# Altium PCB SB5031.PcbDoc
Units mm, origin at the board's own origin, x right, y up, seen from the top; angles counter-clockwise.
Board outline 152.4 x 101.6 mm, 2 copper layers (Top Layer, Bottom Layer); 0 components, 0 nets, 4 pads, 0 vias.
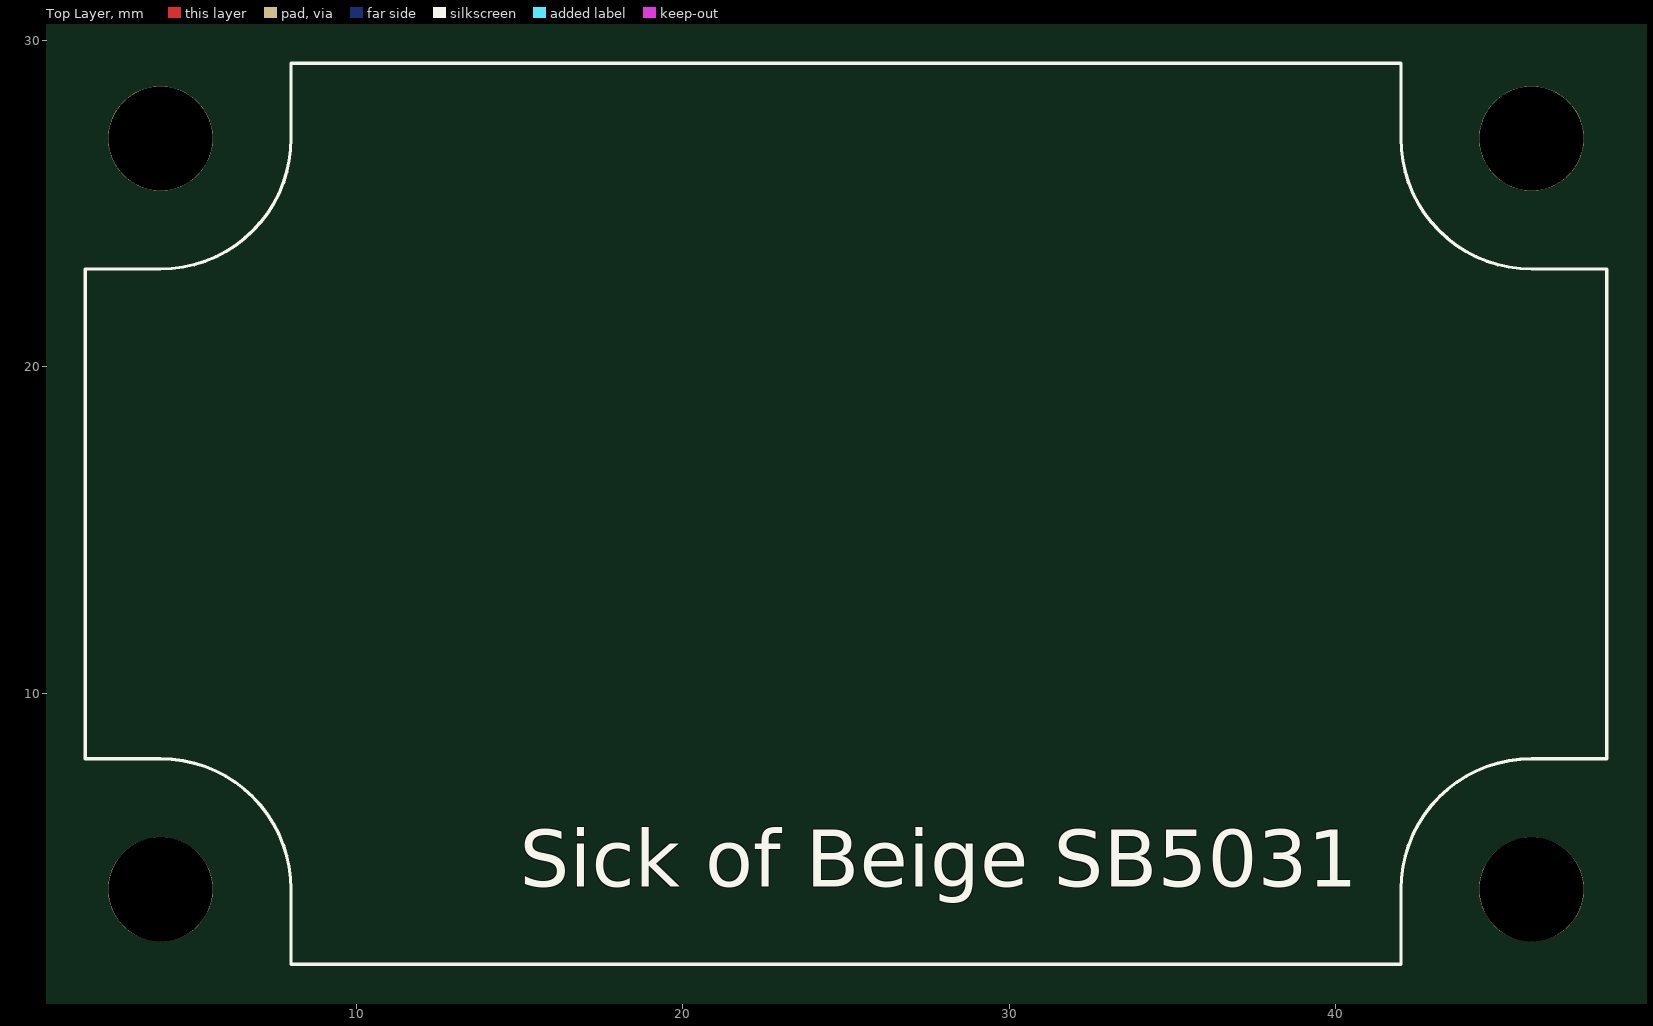
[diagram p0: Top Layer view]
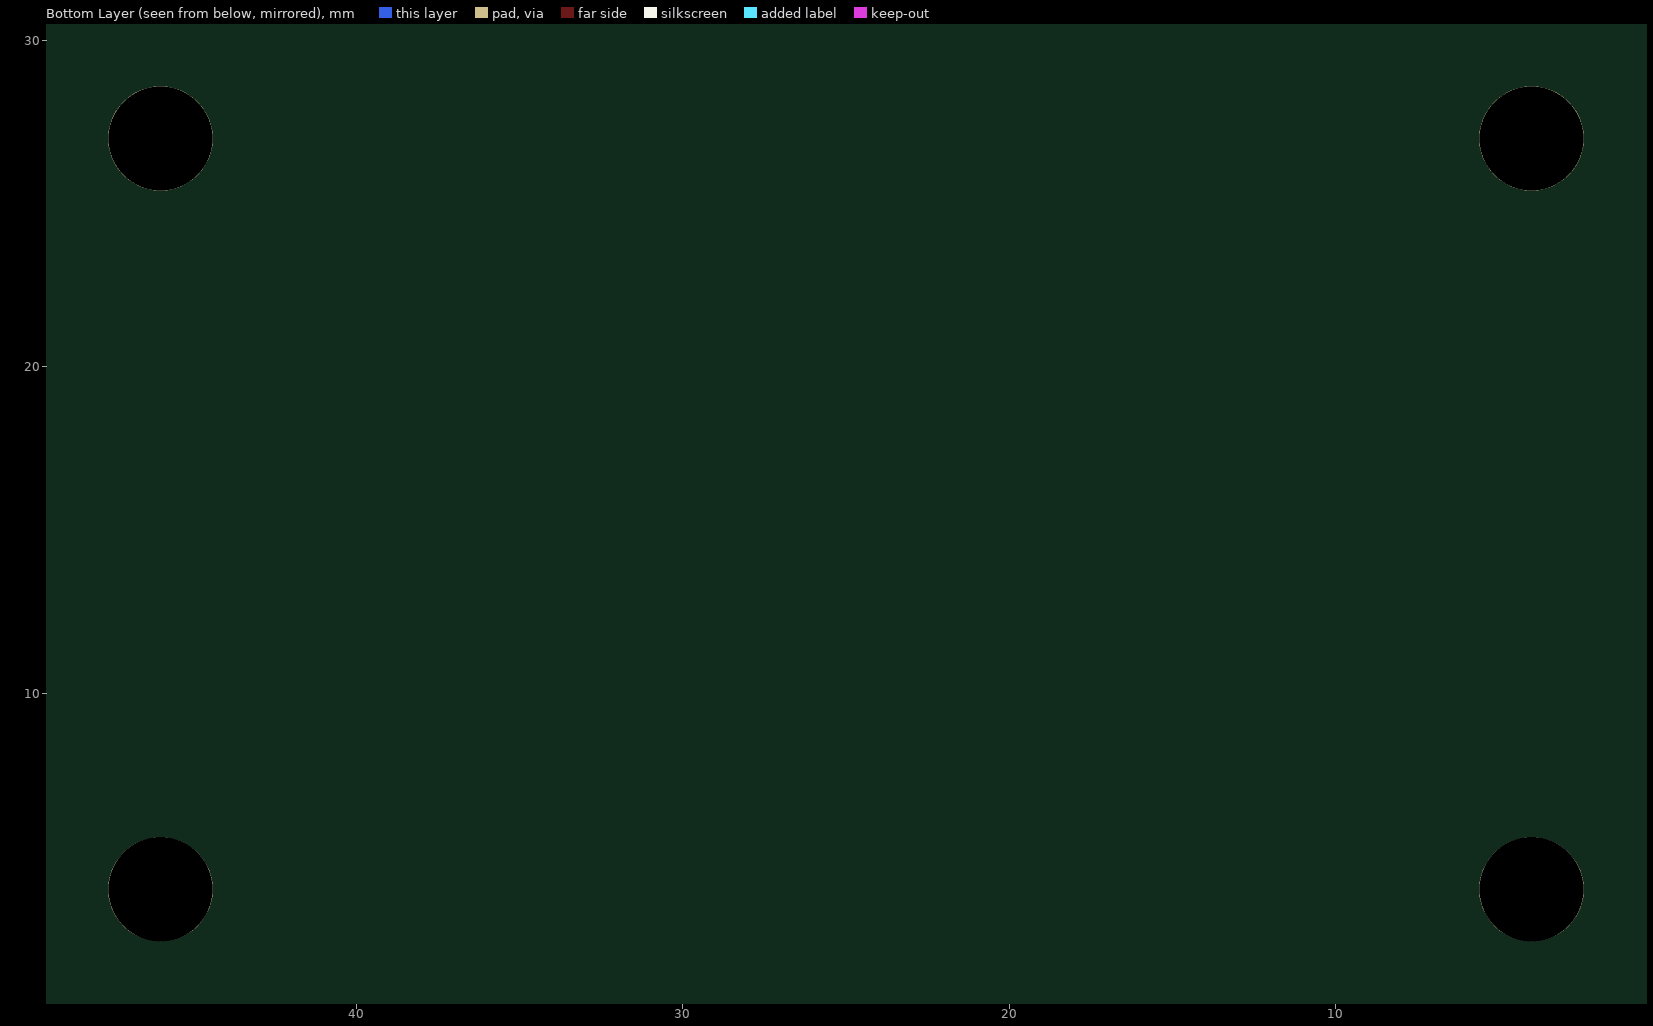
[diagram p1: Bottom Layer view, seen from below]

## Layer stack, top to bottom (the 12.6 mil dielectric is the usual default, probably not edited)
Top Layer: signal copper 0.0356
Dielectric: dielectric 0.32, FR-4, Dk 4.8
Bottom Layer: signal copper 0.0356

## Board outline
-24.6,-29.6 127.8,-29.6 127.8,72 -24.6,72

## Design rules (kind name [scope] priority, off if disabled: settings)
Clearance [All] p1: gap=0.254
PolygonConnect [All] p1: connectstyle=Relief reliefconductorwidth=0.254 reliefentries=4 polygonreliefangle="90 Angle" airgapwidth=0.254
RoutingVias [All] p1: holewidth=0.711 width=1.27 viastyle="Through Hole" minholewidth=0.711 minwidth=1.27 maxholewidth=0.711 maxwidth=1.27
SolderMaskExpansion [All] p1: expansion=0.102
Width [All] p1: maxlimit=0.254 minlimit=0.254 preferedwidth=0.254
28 further rules are at their usual default settings.

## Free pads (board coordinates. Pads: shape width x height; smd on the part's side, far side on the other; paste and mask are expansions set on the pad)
  round 3.2 hole 3.2 unplated: 0(4,4) 1(4,27) 2(46,27) 3(46,4)

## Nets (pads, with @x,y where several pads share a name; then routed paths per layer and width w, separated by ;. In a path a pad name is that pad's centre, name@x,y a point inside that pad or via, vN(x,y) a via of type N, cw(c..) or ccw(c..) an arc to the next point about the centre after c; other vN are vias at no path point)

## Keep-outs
Top Overlay:
  lines w0.102: 1.7,8 4,8 cw(c4,4) 8,4 8,1.7 42,1.7 42,4 cw(c46,4) 46,8 48.3,8 48.3,23 46,23 cw(c46,27) 42,27 42,29.3 8,29.3 8,27 cw(c4,27) 4,23 1.7,23 1.7,8

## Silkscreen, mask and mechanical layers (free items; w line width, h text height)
Top Overlay:
  text "Sick of Beige SB5031" at 15,3.5 h3
Mechanical 1:
  lines w0.102: 0,4 ccw(c4,4) 4,0 46,0 ccw(c46,4) 50,4 50,27 ccw(c46,27) 46,31 4,31 ccw(c4,27) 0,27 0,4
Mechanical 4:
  circle w0.102: c46,4 r1.6
  circle w0.102: c4,4 r1.6
  circle w0.102: c4,27 r1.6
  circle w0.102: c46,27 r1.6
  lines w0.102: 0,15.5 50,15.5 ; 25,0 25,31

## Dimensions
46,31 to 46,0 on Mechanical 3
0,4 to 50,4 on Mechanical 3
